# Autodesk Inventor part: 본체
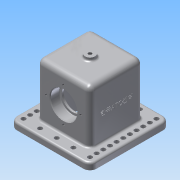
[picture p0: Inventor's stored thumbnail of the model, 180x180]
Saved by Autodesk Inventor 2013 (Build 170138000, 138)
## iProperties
Created: 2018-11
Part Number: 본체
Material: 알루미늄 6061
Document SubType Name: Modeling
Designer: Administrator
Density: 2.71 g/cm^3
Mass: 1020.43 g
Surface Area: 776.966 cm^2
Volume: 376.543 cm^3
Author: Administrator
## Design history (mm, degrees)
sketch "스케치1"
  geometry: L1 (-40, 40)-(40, 40); L2 (40, 40)-(40, -40); L3 (40, -40)-(-40, -40); L4 (-40, -40)-(-40, 40); L5 (-40, 40)-(40, -40); L6 (40, 40)-(-40, -40); 1 further point
  constraints: 12 end point, 2 midpoint, 2 parallel, 2 perpendicular, 1 horizontal
  dimensions: "d0" = 80 distance of L2.end L3.end
extrude "돌출1" new body sketch "스케치1" distance "d2" = 80; taper "d3" = 0 deg
sketch "스케치2"
  geometry: L1 (60, -60)-(-60, -60); L2 (-60, -60)-(-60, 60); L3 (-60, 60)-(60, 60); L4 (60, 60)-(60, -60); L5 (60, -60)-(-60, 60); L6 (-60, -60)-(60, 60); 1 further point
  constraints: 12 end point, 2 midpoint, 2 parallel, 2 perpendicular, 1 horizontal
  dimensions: "d4" = 120 distance of L2.end L3.end
extrude "돌출2" join sketch "스케치2" distance "d6" = 10; taper "d7" = 0 deg
sketch "스케치3"
  geometry: L1 (30, -23)-(-30, -23); L2 (-30, -23)-(-30, 23); L3 (-30, 23)-(30, 23); L4 (30, 23)-(30, -23); L5 (30, -23)-(-30, 23); L6 (-30, -23)-(30, 23); 1 further point
  constraints: 12 end point, 2 midpoint, 2 parallel, 1 horizontal, 1 perpendicular
  dimensions: "d8" = 46 distance of L3.end L1.start; "d10" = 60 distance of L2.end L3.end
extrude "돌출3" cut sketch "스케치3" distance "d11" = 80; taper "d12" = 0 deg
sketch "스케치4"
  geometry: L1 (100, -90)-(-20, -90) reference; 3 further points
  constraints: 1 midpoint, 1 vertical alignment
  dimensions: "d13" = 48 distance from line of point (40, -42) L1
hole "구멍1" sketch "스케치4" at (40, -42) diameter "d14" = 33; stored, may be unused: countersink angle "d18" = 90 deg, drill point angle "d20" = 118 deg; dims "d15" = 6, "d16" = 4, "d17" = 2, "d19" = 8
hole "구멍2" diameter "d23" = 40; stored, may be unused: countersink angle "d27" = 90 deg, drill point angle "d29" = 0 deg; dims "d21" = 10, "d22" = 10, "d24" = 6, "d25" = 4, "d26" = 2, "d28" = 14
sketch "스케치5"
  geometry: C1 r 7.5 at (0, 0); 1 further point
  constraints: 1 centre point, 1 coincident
  dimensions: "d30" = 15 diameter of C1
extrude "돌출4" join sketch "스케치5" distance "d32" = 5; taper "d33" = 0 deg
hole "구멍3" diameter "d36" = 4.917; stored, may be unused: countersink angle "d40" = 90 deg, drill point angle "d42" = 0 deg; dims "d34" = 10, "d35" = 10, "d37" = 6, "d38" = 4, "d39" = 2, "d41" = 14
fillet "모깎기1" dims "d43" = 10
fillet "모깎기2" dims "d44" = 8
fillet "모깎기3" dims "d45" = 8
sketch "스케치6"
  geometry: C1 r 20 at (32, 38) reference; 2 further points
  constraints: 1 vertical alignment
  dimensions: "d46" = 26 distance of point (32, 64) C1.centre
hole "구멍4" sketch "스케치6" at (32, 64) diameter "d47" = 3.242; stored, may be unused: countersink angle "d51" = 90 deg, drill point angle "d53" = 118 deg; dims "d48" = 8, "d49" = 4, "d50" = 2, "d52" = 10
chamfer "모따기1" distance "d57" = 1; stored, may be unused: second distance "d58" = 2, angle "d59" = 45 deg
fillet "모깎기4" dims "d60" = 3
fillet "모깎기5" dims "d61" = 3
fillet "모깎기6" dims "d62" = 0.6
sketch "스케치7"
  geometry: A1 r 7 centre (50, -50) between (50, -57) and (57, -50) reference; A2 r 7 centre (50, 50) between (57, 50) and (50, 57) reference; A3 r 7 centre (-50, 50) between (-50, 57) and (-57, 50) reference; A4 r 7 centre (-50, -50) between (-57, -50) and (-50, -57) reference; 29 further points
  constraints: 22 vertical alignment, 16 horizontal alignment, 4 coincident
  dimensions: "d63" = 25 distance of point (-25, -50) A4.centre; "d64" = 25 distance of point (0, -50) point (-25, -50); "d65" = 25 distance of point (25, -50) point (0, -50); "d66" = 25 distance of A1.centre point (25, -50) (derived); "d67" = 10 distance of point (-50, 40) point (-50, 50); "d68" = 10 distance of point (-50, 30) point (-50, 40); "d69" = 10 distance of point (-50, 20) point (-50, 30); "d70" = 10 distance of point (-50, 10) point (-50, 20); "d71" = 10 distance of point (-50, 0) point (-50, 10); "d72" = 10 distance of point (-50, -10) point (-50, 0); "d73" = 10 distance of point (-50, -20) point (-50, -10); "d74" = 10 distance of point (-50, -30) point (-50, -20); "d75" = 10 distance of point (-50, -40) point (-50, -30)
hole "구멍5" sketch "스케치7" diameter "d76" = 6.6; stored, may be unused: countersink angle "d80" = 90 deg, drill point angle "d82" = 118 deg; dims "d77" = 8, "d78" = 4, "d79" = 2, "d81" = 10
sketch "스케치8"
  geometry: L1 (82, -82)-(-18, -82) reference; 3 further points
  constraints: 1 midpoint, 1 vertical alignment, 1 other
  dimensions: "d83" = 48 distance from line of L1 point (32, -34)
feature "엠보싱1" sketch "스케치8" dims "d0" = 80, "d8" = 46, "d10" = 60, "d84" = 0.5, "d85" = 0
node "솔리드1"
mirror "대칭1"
pattern_circular "원형 패턴1" dims angle "d55" = 360 deg
mirror "대칭2"
